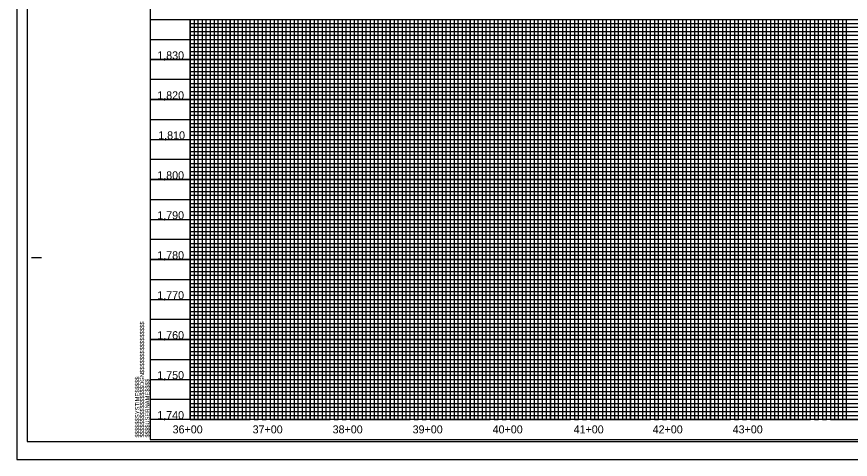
# Model space of a CAD drawing. Extents: x 497599 to 513368, y 404140 to 476034.
# Drawn here: x 505692 to 506734, y 438761 to 439315 of the extents above; entities that cross this region are included whole.
import ezdxf

# ---------------------------------------------------------------- set-up
doc = ezdxf.new("R2010")
doc.units = 0
for name, color, linetype in [('Exist Vertical Profile Vertical Axis Label', 7, 'Continuous'), ('Sheet Cutting Line CELL', 7, 'Continuous'), ('Sheet DOT Grid CELL', 7, 'Continuous'), ('Sheet Layout Profile Border Port 2', 7, 'Continuous'), ('Sheet Plot Border Inside CELL', 7, 'Continuous'), ('Sheet Plot Border Outside CELL', 7, 'Continuous'), ('Sheet Profile CELL', 7, 'Continuous'), ('Sheet Profile Grid Major CELL', 7, 'Continuous'), ('Sheet Profile Grid Middle CELL', 7, 'Continuous'), ('Sheet Profile Grid Minor CELL', 7, 'Continuous')]:
    doc.layers.add(name, color=color, linetype=linetype)

msp = doc.modelspace()

# ---------------------------------------------------------------- linework, layer by layer
at = {"layer": 'Sheet Cutting Line CELL'}
for p, q in [((505691.7, 439861.1), (505691.7, 438761.1)), ((505691.7, 438761.1), (507375.7, 438761.1))]:
    msp.add_line(p, q, dxfattribs=at)
at = {"layer": 'Sheet DOT Grid CELL'}
for p, q in [((505858.7, 439311.1), (507358.6, 439311.1)), ((505908.7, 439311.1), (505908.7, 438811.1)), ((505958.7, 439311.1), (505958.7, 438811.1)), ((506008.7, 439311.1), (506008.7, 438811.1)), ((506058.7, 439311.1), (506058.7, 438811.1)), ((506108.7, 439311.1), (506108.7, 438811.1)), ((506158.7, 439311.1), (506158.7, 438811.1)), ((506208.7, 439311.1), (506208.7, 438811.1)), ((506258.7, 439311.1), (506258.7, 438811.1)), ((506308.7, 439311.1), (506308.7, 438811.1)), ((506358.7, 439311.1), (506358.7, 438811.1)), ((506408.7, 439311.1), (506408.7, 438811.1)), ((506458.7, 439311.1), (506458.7, 438811.1)), ((506508.7, 439311.1), (506508.7, 438811.1)), ((506558.7, 439311.1), (506558.7, 438811.1)), ((506608.7, 439311.1), (506608.7, 438811.1)), ((506658.7, 439311.1), (506658.7, 438811.1)), ((506708.7, 439311.1), (506708.7, 438811.1)), ((505858.7, 439261.1), (507358.6, 439261.1)), ((505858.7, 439211.1), (507358.6, 439211.1)), ((505858.7, 439161.1), (507358.6, 439161.1)), ((505858.7, 439111.1), (507358.6, 439111.1)), ((505858.7, 439061.1), (507358.6, 439061.1)), ((505858.7, 439011.1), (507358.6, 439011.1)), ((505858.7, 438961.1), (507358.6, 438961.1)), ((505858.7, 438911.1), (507358.6, 438911.1)), ((505858.7, 438861.1), (507358.6, 438861.1))]:
    msp.add_line(p, q, dxfattribs=at)
at = {"layer": 'Sheet Layout Profile Border Port 2'}
msp.add_lwpolyline([(505908.7, 439311.1), (507308.7, 439311.1), (507308.7, 438811.1), (505908.7, 438811.1)], close=True, dxfattribs=at)
msp.add_lwpolyline([(505908.7, 439311.1), (507308.7, 439311.1), (507308.7, 438811.1), (505908.7, 438811.1)], close=True, dxfattribs=at)
at = {"layer": 'Sheet Plot Border Inside CELL'}
msp.add_lwpolyline([(505704.7, 438783.6), (507371.2, 438783.6), (507371.2, 439838.7), (505704.7, 439838.7)], close=True, dxfattribs=at)
at = {"layer": 'Sheet Plot Border Outside CELL'}
msp.add_lwpolyline([(505691.7, 438761.1), (507375.7, 438761.1), (507375.7, 439861.1), (505691.7, 439861.1)], close=True, dxfattribs=at)
at = {"layer": 'Sheet Profile CELL'}
for p, q in [((505858.7, 439311.1), (507358.7, 439311.1)), ((505710.2, 439013.6), (505722.7, 439013.6)), ((507358.7, 438811.1), (505858.7, 438811.1)), ((505858.7, 438786.1), (507358.7, 438786.1)), ((505858.7, 438786.1), (505858.7, 438786.1)), ((505858.7, 438786.1), (505858.7, 438786.1)), ((505858.7, 438786.1), (505858.7, 438786.1)), ((505858.7, 438786.1), (505858.7, 438786.1)), ((505858.7, 438786.1), (505858.7, 438786.1)), ((505858.7, 438786.1), (505858.7, 438786.1)), ((505858.7, 438786.1), (505858.7, 438786.1))]:
    msp.add_line(p, q, dxfattribs=at)
msp.add_lwpolyline([(507358.7, 439836.1), (505858.7, 439836.1), (505858.7, 438786.1), (507358.7, 438786.1)], close=True, dxfattribs=at)
msp.add_lwpolyline([(505896.2, 438786.1), (505896.2, 438786.1)], dxfattribs=at)
at = {"layer": 'Sheet Profile Grid Major CELL'}
for p, q in [((506558.7, 439311.1), (506608.7, 439311.1)), ((506558.7, 439311.1), (506608.7, 439311.1)), ((506658.7, 439311.1), (506708.7, 439311.1)), ((506658.7, 439311.1), (506708.7, 439311.1)), ((505858.7, 438811.1), (505858.7, 438811.1))]:
    msp.add_line(p, q, dxfattribs=at)
for points in [[(505908.7, 439311.1), (505908.7, 438811.1), (505958.7, 438811.1), (505958.7, 439311.1), (506008.7, 439311.1), (506008.7, 438811.1), (506058.7, 438811.1), (506058.7, 439311.1), (506108.7, 439311.1), (506108.7, 438811.1), (506158.7, 438811.1), (506158.7, 439311.1), (506208.7, 439311.1), (506208.7, 438811.1), (506258.7, 438811.1), (506258.7, 439311.1), (506308.7, 439311.1), (506308.7, 438811.1), (506358.7, 438811.1), (506358.7, 439311.1), (506408.7, 439311.1), (506408.7, 438811.1), (506458.7, 438811.1), (506458.7, 439311.1), (506508.7, 439311.1), (506508.7, 438811.1), (506558.7, 438811.1), (506558.7, 439311.1), (506608.7, 439311.1), (506608.7, 438811.1), (506658.7, 438811.1), (506658.7, 439311.1), (506708.7, 439311.1), (506708.7, 438811.1), (506758.7, 438811.1)], [(507358.7, 439261.1), (505858.7, 439261.1)], [(507358.7, 439211.1), (505858.7, 439211.1), (505858.7, 439161.1), (507358.7, 439161.1)], [(507358.7, 439111.1), (505858.7, 439111.1), (505858.7, 439061.1), (507358.7, 439061.1)], [(507358.7, 439011.1), (505858.7, 439011.1), (505858.7, 438961.1), (507358.7, 438961.1)], [(507358.7, 438911.1), (505858.7, 438911.1), (505858.7, 438911.1), (505858.7, 438861.1), (507358.7, 438861.1)], [(507358.7, 438811.1), (505858.7, 438811.1)]]:
    msp.add_lwpolyline(points, dxfattribs=at)
at = {"layer": 'Sheet Profile Grid Middle CELL'}
for points in [[(505883.7, 439311.1), (505933.7, 439311.1), (505933.7, 438811.1), (505983.7, 438811.1), (505983.7, 439311.1), (506033.7, 439311.1), (506033.7, 438811.1), (506083.7, 438811.1), (506083.7, 439311.1), (506133.7, 439311.1), (506133.7, 438811.1), (506183.7, 438811.1), (506183.7, 439311.1), (506233.7, 439311.1), (506233.7, 438811.1), (506283.7, 438811.1), (506283.7, 439311.1), (506333.7, 439311.1), (506333.7, 438811.1), (506383.7, 438811.1), (506383.7, 439311.1), (506433.7, 439311.1), (506433.7, 438811.1), (506483.7, 438811.1), (506483.7, 438811.1), (506483.7, 439311.1), (506533.7, 439311.1), (506533.7, 438811.1), (506583.7, 438811.1), (506583.7, 439311.1), (506633.7, 439311.1), (506633.7, 438811.1), (506683.7, 438811.1), (506683.7, 439311.1), (506733.7, 439311.1)], [(505858.7, 439286.1), (507358.7, 439286.1)], [(507358.7, 439236.1), (505858.7, 439236.1), (505858.7, 439186.1), (507358.7, 439186.1)], [(507358.7, 439136.1), (505858.7, 439136.1), (505858.7, 439086.1), (507358.7, 439086.1)], [(507358.7, 439036.1), (505858.7, 439036.1), (505858.7, 438986.1), (507358.7, 438986.1)], [(507358.7, 438936.1), (505858.7, 438936.1), (505858.7, 438886.1), (507358.7, 438886.1)], [(507358.7, 438836.1), (505858.7, 438836.1)]]:
    msp.add_lwpolyline(points, dxfattribs=at)
at = {"layer": 'Sheet Profile Grid Minor CELL'}
for p, q in [((505908.7, 439306.1), (507308.7, 439306.1)), ((507308.7, 439301.1), (505908.7, 439301.1)), ((505908.7, 439296.1), (507308.7, 439296.1)), ((507308.7, 439291.1), (505908.7, 439291.1)), ((505908.7, 439281.1), (507308.7, 439281.1)), ((507308.7, 439276.1), (505908.7, 439276.1)), ((505908.7, 439271.1), (507308.7, 439271.1)), ((507308.7, 439266.1), (505908.7, 439266.1)), ((505908.7, 439256.1), (507308.7, 439256.1)), ((507308.7, 439251.1), (505908.7, 439251.1)), ((505908.7, 439246.1), (507308.7, 439246.1)), ((507308.7, 439241.1), (505908.7, 439241.1)), ((505908.7, 439231.1), (507308.7, 439231.1)), ((507308.7, 439226.1), (505908.7, 439226.1)), ((505908.7, 439221.1), (507308.7, 439221.1)), ((507308.7, 439216.1), (505908.7, 439216.1)), ((505908.7, 439206.1), (507308.7, 439206.1)), ((507308.7, 439201.1), (505908.7, 439201.1)), ((505908.7, 439196.1), (507308.7, 439196.1)), ((507308.7, 439191.1), (505908.7, 439191.1)), ((505908.7, 439181.1), (507308.7, 439181.1)), ((507308.7, 439176.1), (505908.7, 439176.1)), ((505908.7, 439171.1), (507308.7, 439171.1)), ((507308.7, 439166.1), (505908.7, 439166.1)), ((505908.7, 439156.1), (507308.7, 439156.1)), ((507308.7, 439151.1), (505908.7, 439151.1)), ((505908.7, 439146.1), (507308.7, 439146.1)), ((507308.7, 439141.1), (505908.7, 439141.1)), ((505908.7, 439131.1), (507308.7, 439131.1)), ((507308.7, 439126.1), (505908.7, 439126.1)), ((505908.7, 439121.1), (507308.7, 439121.1)), ((507308.7, 439116.1), (505908.7, 439116.3)), ((505908.7, 439106.1), (507308.7, 439106.1)), ((507308.7, 439101.1), (505908.7, 439101.1)), ((505908.7, 439096.1), (507308.7, 439096.1)), ((507308.7, 439091.1), (505908.7, 439091.1)), ((505908.7, 439081.1), (507308.7, 439081.1)), ((507308.7, 439076.1), (505908.7, 439076.1)), ((505908.7, 439071.1), (507308.7, 439071.1)), ((507308.7, 439066.1), (505908.7, 439066.1)), ((505908.7, 439056.1), (507308.7, 439056.1)), ((507308.7, 439051.1), (505908.7, 439051.1)), ((505908.7, 439046.1), (507308.7, 439046.1)), ((507308.7, 439041.1), (505908.7, 439041.1)), ((505908.7, 439031.1), (507308.7, 439031.1)), ((507308.7, 439026.1), (505908.7, 439026.1)), ((505908.7, 439021.1), (507308.7, 439021.1)), ((507308.7, 439016.1), (505908.7, 439016.1)), ((505908.7, 439006.1), (507308.7, 439006.1)), ((507308.7, 439001.1), (505908.7, 439001.1)), ((505908.7, 438996.1), (507308.7, 438996.1)), ((507308.7, 438991.1), (505908.7, 438991.1)), ((505908.7, 438981.1), (507308.7, 438981.1)), ((507308.7, 438976.1), (505908.7, 438976.1)), ((505908.7, 438971.1), (507308.7, 438971.1)), ((507308.7, 438966.1), (505908.7, 438966.1)), ((505908.7, 438956.1), (507308.7, 438956.1)), ((507308.7, 438951.1), (505908.7, 438951.1)), ((505908.7, 438946.1), (507308.7, 438946.1)), ((507308.7, 438941.1), (505908.7, 438941.1)), ((505908.7, 438931.1), (507308.7, 438931.1)), ((507308.7, 438926.1), (505908.7, 438926.1)), ((505908.7, 438921.1), (507308.7, 438921.1)), ((507308.7, 438916.1), (505908.7, 438916.1)), ((505908.7, 438906.1), (507308.7, 438906.1)), ((507308.7, 438901.1), (505908.7, 438901.1)), ((505908.7, 438896.1), (507308.7, 438896.1)), ((507308.7, 438891.1), (505908.7, 438891.1)), ((505908.7, 438881.1), (507308.7, 438881.1)), ((507308.7, 438876.1), (505908.7, 438876.1)), ((505908.7, 438871.1), (507308.7, 438871.1)), ((507308.7, 438866.1), (505908.7, 438866.1)), ((505908.7, 438856.1), (507308.7, 438856.1)), ((507308.7, 438851.1), (505908.7, 438851.1)), ((505908.7, 438846.1), (507308.7, 438846.1)), ((507308.7, 438841.1), (505908.7, 438841.1)), ((505908.7, 438831.1), (507308.7, 438831.1)), ((507308.7, 438826.1), (505908.7, 438826.1)), ((505908.7, 438821.1), (507308.7, 438821.1)), ((505908.7, 438816.1), (507308.7, 438816.1))]:
    msp.add_line(p, q, dxfattribs=at)
for points in [[(505908.7, 439311.1), (505913.7, 439311.1), (505913.7, 438811.1), (505918.7, 438811.1), (505918.7, 439311.1), (505923.7, 439311.1), (505923.7, 438811.1), (505928.7, 438811.1), (505928.7, 439311.1), (505938.7, 439311.1), (505938.7, 438811.1), (505943.7, 438811.1), (505943.7, 439311.1), (505948.7, 439311.1), (505948.7, 438811.1), (505953.7, 438811.1), (505963.7, 438811.1), (505968.7, 438811.1), (505968.7, 439311.1), (505973.7, 439311.1), (505973.7, 438811.1), (505978.7, 438811.1), (505978.7, 439311.1), (505988.7, 439311.1), (505988.7, 438811.1), (505993.7, 438811.1), (505993.7, 439311.1), (505998.7, 439311.1), (505998.7, 438811.1), (506003.7, 438811.1), (506003.7, 439311.1), (506013.7, 439311.1), (506013.7, 438811.1), (506018.7, 438811.1), (506018.7, 439311.1), (506023.7, 439311.1), (506023.7, 438811.1), (506028.7, 438811.1), (506028.7, 439311.1), (506038.7, 439311.1), (506038.7, 438811.1), (506043.7, 438811.1), (506043.7, 439311.1), (506048.7, 439311.1), (506048.7, 438811.1), (506053.7, 438811.1), (506053.7, 439311.1), (506063.7, 439311.1), (506063.7, 438811.1), (506068.7, 438811.1), (506068.7, 439311.1), (506073.7, 439311.1), (506073.7, 438811.1), (506078.7, 438811.1), (506078.7, 439311.1), (506088.7, 439311.1), (506088.7, 438811.1), (506093.7, 438811.1), (506093.7, 439311.1), (506098.7, 439311.1), (506098.7, 438811.1), (506103.7, 438811.1), (506103.7, 439311.1), (506113.7, 439311.1), (506113.7, 438811.1), (506118.7, 438811.1), (506118.7, 439311.1), (506123.7, 439311.1), (506123.7, 438811.1)], [(505953.7, 438811.1), (505953.7, 439311.1), (505963.7, 439311.1), (505963.7, 438811.1)], [(506123.7, 438811.1), (506128.7, 438811.1), (506128.7, 439311.1), (506138.7, 439311.1), (506138.7, 438811.1), (506143.7, 438811.1), (506143.7, 439311.1), (506148.7, 439311.1), (506148.7, 438811.1), (506153.7, 438811.1), (506153.7, 439311.1), (506163.7, 439311.1), (506163.7, 438811.1), (506168.7, 438811.1), (506168.7, 439311.1), (506173.7, 439311.1), (506173.7, 438811.1), (506178.7, 438811.1), (506178.7, 439311.1), (506188.7, 439311.1), (506188.7, 438811.1), (506193.7, 438811.1), (506193.7, 439311.1), (506198.7, 439311.1), (506198.7, 438811.1), (506203.7, 438811.1), (506203.7, 439311.1), (506213.7, 439311.1), (506213.7, 438811.1), (506218.7, 438811.1), (506218.7, 439311.1), (506223.7, 439311.1), (506223.7, 438811.1), (506228.7, 438811.1), (506228.7, 439311.1), (506238.7, 439311.1), (506238.7, 438811.1), (506243.7, 438811.1), (506243.7, 439311.1), (506248.7, 439311.1), (506248.7, 438811.1), (506253.7, 438811.1), (506253.7, 439311.1), (506263.7, 439311.1), (506263.7, 438811.1), (506268.7, 438811.1), (506268.7, 439311.1), (506273.7, 439311.1), (506273.7, 438811.1), (506278.7, 438811.1), (506278.7, 439311.1), (506288.7, 439311.1), (506288.7, 438811.1), (506293.7, 438811.1), (506293.7, 439311.1), (506298.7, 439311.1), (506298.7, 438811.1), (506303.7, 438811.1), (506303.7, 439311.1), (506313.7, 439311.1), (506313.7, 438811.1), (506318.7, 438811.1), (506318.7, 439311.1), (506323.7, 439311.1), (506323.7, 438811.1), (506328.7, 438811.1), (506328.7, 439311.1), (506338.7, 439311.1), (506338.7, 438811.1), (506343.7, 438811.1), (506343.7, 439311.1), (506348.7, 439311.1), (506348.7, 438811.1), (506353.7, 438811.1), (506353.7, 439311.1), (506363.7, 439311.1), (506363.7, 438811.1), (506368.7, 438811.1), (506368.7, 439311.1), (506373.7, 439311.1), (506373.7, 438811.1), (506378.7, 438811.1), (506378.7, 439311.1), (506388.7, 439311.1), (506388.7, 438811.1), (506393.7, 438811.1), (506393.7, 439311.1), (506398.7, 439311.1), (506398.7, 438811.1), (506403.7, 438811.1), (506403.7, 439311.1), (506413.7, 439311.1), (506413.7, 438811.1), (506418.7, 438811.1), (506418.7, 439311.1), (506423.7, 439311.1), (506423.7, 438811.1), (506428.7, 438811.1), (506428.7, 439311.1), (506438.7, 439311.1)], [(506438.7, 439311.1), (506438.7, 438811.1), (506443.7, 438811.1), (506443.7, 439311.1), (506448.7, 439311.1), (506448.7, 438811.1), (506453.7, 438811.1), (506453.7, 439311.1), (506463.7, 439311.1), (506463.7, 438811.1), (506468.7, 438811.1), (506468.7, 439311.1), (506473.7, 439311.1), (506473.7, 438811.1), (506478.7, 438811.1), (506478.7, 439311.1), (506488.7, 439311.1), (506488.7, 438811.1), (506493.7, 438811.1), (506493.7, 439311.1), (506498.7, 439311.1), (506498.7, 438811.1), (506503.7, 438811.1), (506503.7, 439311.1), (506513.7, 439311.1), (506513.7, 438811.1), (506518.7, 438811.1), (506518.7, 439311.1), (506523.7, 439311.1), (506523.7, 438811.1), (506528.7, 438811.1), (506528.7, 439311.1), (506538.7, 439311.1), (506538.7, 438811.1), (506543.7, 438811.1), (506543.7, 439311.1), (506548.7, 439311.1), (506548.7, 438811.1), (506553.7, 438811.1), (506553.7, 439311.1), (506563.7, 439311.1), (506563.7, 438811.1), (506563.7, 438811.1), (506568.7, 438811.1), (506568.7, 439311.1), (506573.7, 439311.1), (506573.7, 438811.1), (506578.7, 438811.1), (506578.7, 439311.1), (506588.7, 439311.1), (506588.7, 438811.1), (506593.7, 438811.1), (506593.7, 439311.1), (506598.7, 439311.1), (506598.7, 438811.1), (506603.7, 438811.1), (506603.7, 439311.1), (506613.7, 439311.1), (506613.7, 438811.1), (506618.7, 438811.1), (506618.7, 439311.1), (506623.7, 439311.1), (506623.7, 438811.1), (506628.7, 438811.1), (506628.7, 439311.1), (506638.7, 439311.1), (506638.7, 438811.1), (506643.7, 438811.1), (506643.7, 439311.1), (506648.7, 439311.1), (506648.7, 438811.1), (506653.7, 438811.1), (506653.7, 439311.1), (506663.7, 439311.1), (506663.7, 438811.1), (506668.7, 438811.1), (506668.7, 439311.1), (506673.7, 439311.1), (506673.7, 438811.1), (506678.7, 438811.1), (506678.7, 439311.1), (506688.7, 439311.1), (506688.7, 438811.1), (506693.7, 438811.1), (506693.7, 439311.1), (506698.7, 439311.1), (506698.7, 438811.1), (506703.7, 438811.1), (506703.7, 439311.1), (506713.7, 439311.1), (506713.7, 438811.1), (506718.4, 438811.7), (506718.7, 438811.1), (506718.7, 439311.1), (506723.7, 439311.1), (506723.7, 438811.1), (506728.7, 438811.1), (506728.7, 439311.1), (506738.7, 439311.1)]]:
    msp.add_lwpolyline(points, dxfattribs=at)

# ---------------------------------------------------------------- texts
at = {"layer": 'Exist Vertical Profile Vertical Axis Label'}
for s, p in [('1,830', (505867.4, 439261.4)), ('1,820', (505867.4, 439211.4)), ('1,810', (505868.6, 439161.4)), ('1,800', (505867.4, 439111.4)), ('1,790', (505867.4, 439061.4)), ('1,780', (505867.4, 439011.4)), ('1,770', (505867.4, 438961.4)), ('1,760', (505867.4, 438911.4)), ('1,750', (505867.4, 438861.4)), ('1,740', (505867.4, 438811.4)), ('36+00', (505886.6, 438793.6)), ('37+00', (505986.6, 438793.6)), ('38+00', (506086.6, 438793.6)), ('39+00', (506186.6, 438793.6)), ('40+00', (506286.6, 438793.6)), ('41+00', (506387.8, 438793.6)), ('42+00', (506486.6, 438793.6)), ('43+00', (506586.6, 438793.6))]:
    msp.add_text(s, height=10, dxfattribs=at).set_placement(p)
at = {"layer": 'Sheet Profile CELL'}
for s, p in [('$$$$$$$$$$$$$$$$DGN$$$$$$$$$$$$$$$$', (505851, 438788.5)), ('$$$$$$SYSTIME$$$$$', (505845, 438788.5)), ('$$$$USERNAME$$$$', (505857.6, 438788.5))]:
    msp.add_text(s, height=5.25, rotation=90, dxfattribs=at).set_placement(p)

doc.saveas('drawing.dxf')
